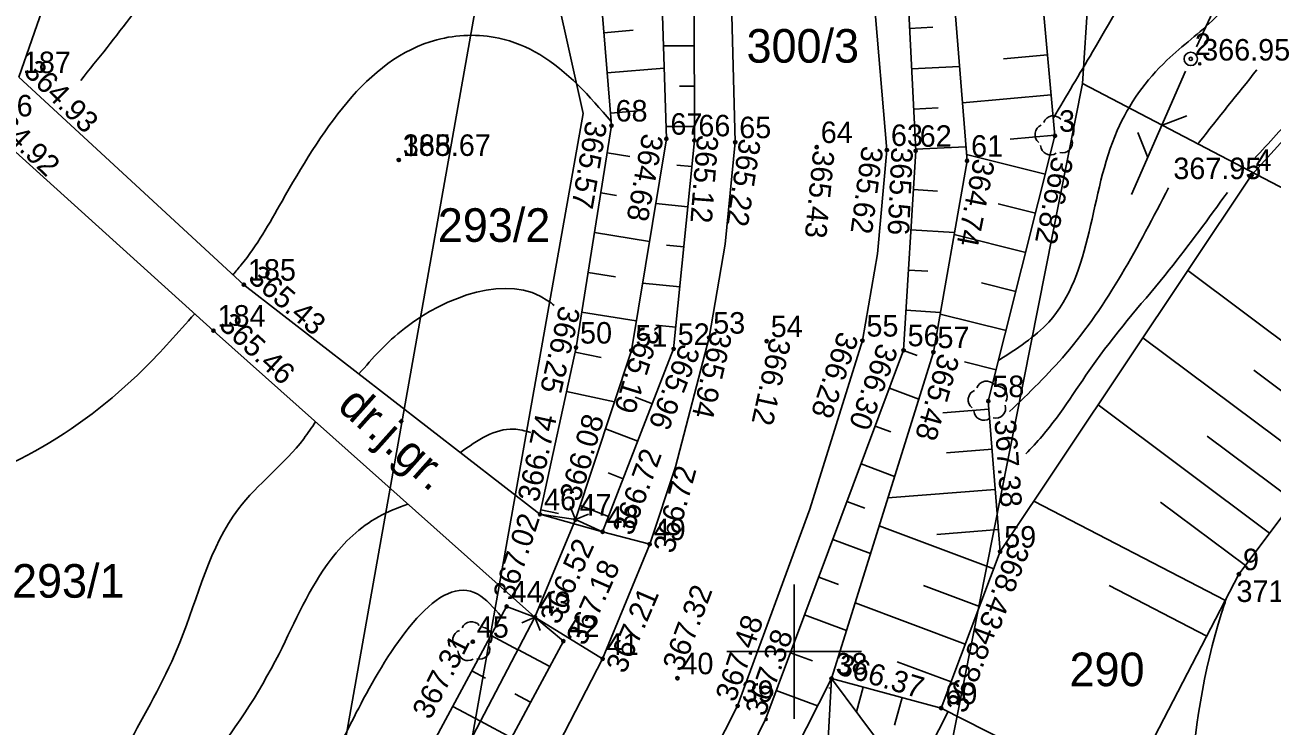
# Model space of a CAD drawing. Extents: x 4635329 to 4651863, y 5356628 to 5367582.
# Drawn here: x 4651721.4 to 4651767.77, y 5357047.23 to 5357073.31 of the extents above; entities that cross this region are included whole.
import ezdxf

# ---------------------------------------------------------------- set-up
doc = ezdxf.new("R2010")
doc.units = 0
for name, color, linetype in [('Level 20', 7, 'Continuous'), ('Level 21', 7, 'Continuous'), ('Level 24', 7, 'Continuous'), ('Level 32', 7, 'Continuous'), ('Level 4', 7, 'Continuous'), ('Level 44', 7, 'Continuous'), ('Level 45', 7, 'Continuous'), ('Level 46', 7, 'Continuous'), ('Level 48', 7, 'Continuous'), ('Level 5', 7, 'Continuous'), ('Level 50', 7, 'Continuous'), ('Level 55', 7, 'Continuous'), ('Level 60', 7, 'Continuous'), ('Level 63', 7, 'Continuous')]:
    doc.layers.add(name, color=color, linetype=linetype)

msp = doc.modelspace()

# ---------------------------------------------------------------- linework, layer by layer
at = {"layer": 'Level 20'}
for p, q in [((4651752.38, 5357081.18), (4651753.45, 5357068.66)), ((4651747.9, 5357047.98), (4651742.26, 5357036.94))]:
    msp.add_line(p, q, dxfattribs=at)
for points in [[(4651729.32, 5357025.03), (4651737.42, 5357039.16), (4651742.88, 5357049.73), (4651744.63, 5357054), (4651745.586, 5357056.87), (4651746.84, 5357061.68), (4651747.431, 5357065.159), (4651747.81, 5357068.95), (4651747.54, 5357079.35), (4651746.07, 5357086.39), (4651738.98, 5357107.74), (4651737.87, 5357110.18), (4651736.57, 5357115.87), (4651735.37, 5357118.93)], [(4651724.46, 5357080.82), (4651721.17, 5357071.37)], [(4651744.63, 5357054), (4651742.88, 5357054.46), (4651740.55, 5357055.11), (4651729.54, 5357063.65), (4651721.17, 5357071.37)], [(4651719.75, 5357069.76), (4651728.41, 5357061.94), (4651740.36, 5357051.28), (4651742.88, 5357049.73)], [(4651753.45, 5357068.66), (4651753.095, 5357064.795), (4651752.54, 5357061.57)], [(4651752.54, 5357061.57), (4651750.584, 5357055.295), (4651747.9, 5357047.98)]]:
    msp.add_lwpolyline(points, dxfattribs=at)
at = {"layer": 'Level 24'}
for p, q in [((4651741.87, 5357054.91), (4651741.668, 5357055.4)), ((4651742.36, 5357055.112), (4651741.87, 5357054.91)), ((4651741.87, 5357054.91), (4651740.36, 5357051.28)), ((4651739.87, 5357051.078), (4651740.36, 5357051.28)), ((4651740.36, 5357051.28), (4651740.562, 5357050.79))]:
    msp.add_line(p, q, dxfattribs=at)
at = {"layer": 'Level 32'}
for p, q in [((4651764.961, 5357072.503), (4651767.07, 5357077.037)), ((4651764.55, 5357071.592), (4651762.549, 5357067.009)), ((4651763.667, 5357069.569), (4651764.598, 5357069.934)), ((4651763.149, 5357068.384), (4651762.784, 5357069.315))]:
    msp.add_line(p, q, dxfattribs=at)
msp.add_circle((4651764.75, 5357072.05), 0.25, dxfattribs=at)
at = {"layer": 'Level 4'}
for p, q in [((4651739.54, 5357081.79), (4651731.74, 5357037.85)), ((4651742.153, 5357070.018), (4651739.54, 5357081.79)), ((4651760.94, 5357074.531), (4651760.729, 5357071.135)), ((4651760.729, 5357071.135), (4651755.332, 5357043.962)), ((4651760.729, 5357071.135), (4651781.491, 5357060.254)), ((4651737.245, 5357042.436), (4651742.153, 5357070.018))]:
    msp.add_line(p, q, dxfattribs=at)
at = {"layer": 'Level 44'}
for centre in [(4651765.083, 5357071.868), (4651743.21, 5357069.57), (4651745.25, 5357069.08), (4651746.29, 5357069.02), (4651747.81, 5357068.95), (4651759.7, 5357069.19), (4651750.84, 5357068.77), (4651753.45, 5357068.66), (4651754.52, 5357068.63), (4651735.3, 5357068.29), (4651756.43, 5357068.26), (4651767.01, 5357067.73), (4651729.54, 5357063.65), (4651728.41, 5357061.94), (4651746.84, 5357061.68), (4651748.98, 5357061.55), (4651752.54, 5357061.57), (4651741.89, 5357061.31), (4651743.95, 5357061.2), (4651745.52, 5357061.26), (4651754.07, 5357061.21), (4651755.18, 5357061.14), (4651757.22, 5357059.32), (4651740.55, 5357055.11), (4651741.87, 5357054.91), (4651742.88, 5357054.46), (4651744.63, 5357054), (4651757.66, 5357053.72), (4651766.54, 5357052.88), (4651739.31, 5357051.68), (4651740.36, 5357051.28), (4651741.42, 5357050.39), (4651738.05, 5357050.37), (4651742.88, 5357049.73), (4651745.66, 5357049.01), (4651751.39, 5357049), (4651747.9, 5357047.98), (4651755.47, 5357047.9), (4651748.961, 5357047.48)]:
    msp.add_circle(centre, 0.04, dxfattribs=at)
at = {"layer": 'Level 46'}
for points in [[(4651759.64, 5357069.854), (4651761.095, 5357072.307), (4651763.521, 5357076.401), (4651765.794, 5357079.585), (4651768.674, 5357082.223), (4651772.525, 5357084.498), (4651783.153, 5357090.274), (4651784.378, 5357091.117)], [(4651723.473, 5357071.251), (4651725.409, 5357073.711), (4651731.503, 5357081.232), (4651732.299, 5357081.873)], [(4651757.599, 5357060.829), (4651759.467, 5357062.262), (4651762.013, 5357069.388), (4651763.863, 5357071.997), (4651765.651, 5357073.573), (4651768.501, 5357077.425), (4651770.563, 5357079.778)], [(4651767.105, 5357068.328), (4651768.709, 5357070.15), (4651771.135, 5357073.607), (4651771.248, 5357073.748)], [(4651743.198, 5357069.717), (4651740.539, 5357072.214), (4651739.023, 5357072.821), (4651736.719, 5357072.76), (4651730.959, 5357066.756), (4651729.443, 5357064.39), (4651729.134, 5357064.025)], [(4651764.995, 5357068.861), (4651765.063, 5357068.948), (4651767.21, 5357071.644)], [(4651758.015, 5357058.929), (4651760.096, 5357061.072), (4651763.924, 5357067.256)], [(4651758.618, 5357057.356), (4651759.22, 5357058.019), (4651761.221, 5357060.809), (4651763.95, 5357064.206), (4651766.113, 5357067.084)], [(4651766.724, 5357038.681), (4651767.527, 5357043.066), (4651768.496, 5357049.151), (4651769.132, 5357051.698), (4651771.164, 5357054.488), (4651775.611, 5357060.263), (4651778.248, 5357062.295), (4651781.341, 5357064.6), (4651784.16, 5357065.358), (4651784.354, 5357065.321)], [(4651733.818, 5357060.331), (4651735.51, 5357062.024), (4651740.846, 5357063.055), (4651741.076, 5357062.881)], [(4651727.711, 5357062.571), (4651725.805, 5357060.508), (4651717.074, 5357055.838), (4651713.254, 5357055.717), (4651704.374, 5357054.513), (4651699.766, 5357053.179), (4651694.309, 5357052.33), (4651693.661, 5357052)], [(4651725.331, 5357046.729), (4651727.157, 5357050.339), (4651729.34, 5357055.312), (4651731.765, 5357057.92), (4651732.207, 5357058.553)], [(4651737.589, 5357057.407), (4651739.57, 5357058.277), (4651740.204, 5357058.158)], [(4651694.191, 5357036.621), (4651700.772, 5357038.944), (4651708.048, 5357039.732), (4651714.051, 5357039.49), (4651719.144, 5357039.793), (4651728.057, 5357045.676), (4651730.846, 5357049.922), (4651732.786, 5357053.44), (4651734.545, 5357055.017), (4651735.638, 5357055.492)], [(4651739.11, 5357051.308), (4651738.239, 5357052.138), (4651733.994, 5357048.256), (4651732.66, 5357045.769), (4651728.598, 5357041.705), (4651724.147, 5357038.834)], [(4651764.562, 5357041.452), (4651764.711, 5357044.761), (4651765.893, 5357051.433), (4651766.067, 5357051.967)]]:
    msp.add_spline(points, degree=3, dxfattribs=at)
at = {"layer": 'Level 48'}
for p, q in [((4651754.293, 5357073.181), (4651755.161, 5357073.224)), ((4651742.925, 5357073.025), (4651744.021, 5357073.115)), ((4651746.283, 5357072.538), (4651745.138, 5357072.536)), ((4651754.368, 5357071.683), (4651756.148, 5357071.771)), ((4651759.426, 5357072.204), (4651757.782, 5357072.054)), ((4651743.048, 5357071.53), (4651745.165, 5357071.704)), ((4651746.286, 5357071.038), (4651745.736, 5357071.037)), ((4651759.562, 5357070.71), (4651756.257, 5357070.409)), ((4651743.172, 5357070.035), (4651744.193, 5357070.119)), ((4651754.442, 5357070.184), (4651755.355, 5357070.23)), ((4651746.289, 5357069.538), (4651745.236, 5357069.536)), ((4651759.698, 5357069.216), (4651758.037, 5357069.065)), ((4651743.047, 5357068.549), (4651743.886, 5357068.415)), ((4651754.517, 5357068.686), (4651756.388, 5357068.78)), ((4651746.193, 5357068.043), (4651745.645, 5357068.097)), ((4651759.341, 5357067.761), (4651756.41, 5357068.497)), ((4651754.433, 5357067.189), (4651755.328, 5357067.135)), ((4651742.81, 5357067.068), (4651743.398, 5357066.974)), ((4651746.045, 5357066.55), (4651744.852, 5357066.669)), ((4651758.975, 5357066.306), (4651757.592, 5357066.653)), ((4651742.574, 5357065.587), (4651744.62, 5357065.26)), ((4651754.342, 5357065.692), (4651755.962, 5357065.593)), ((4651758.61, 5357064.851), (4651755.949, 5357065.52)), ((4651745.897, 5357065.058), (4651745.252, 5357065.122)), ((4651742.337, 5357064.106), (4651743.356, 5357063.943)), ((4651754.251, 5357064.194), (4651754.976, 5357064.151)), ((4651771.276, 5357059.209), (4651764.638, 5357064.176)), ((4651745.749, 5357063.565), (4651744.363, 5357063.703)), ((4651758.244, 5357063.396), (4651756.967, 5357063.717)), ((4651742.1, 5357062.625), (4651744.132, 5357062.3)), ((4651754.16, 5357062.697), (4651755.44, 5357062.62)), ((4651757.879, 5357061.941), (4651755.429, 5357062.557)), ((4651745.601, 5357062.072), (4651744.859, 5357062.146)), ((4651769.479, 5357056.807), (4651762.97, 5357061.677)), ((4651741.854, 5357061.145), (4651742.824, 5357060.936)), ((4651754.066, 5357061.201), (4651754.574, 5357061.011)), ((4651757.513, 5357060.487), (4651756.337, 5357060.782)), ((4651770.377, 5357058.008), (4651767.091, 5357060.467)), ((4651753.541, 5357059.796), (4651754.633, 5357059.387)), ((4651741.537, 5357059.679), (4651743.32, 5357059.294)), ((4651744.73, 5357059.224), (4651744.095, 5357059.471)), ((4651757.243, 5357059.024), (4651755.534, 5357058.889)), ((4651767.681, 5357054.405), (4651761.303, 5357059.178)), ((4651753.015, 5357058.391), (4651753.6, 5357058.172)), ((4651744.187, 5357057.826), (4651742.988, 5357058.291)), ((4651768.58, 5357055.606), (4651765.358, 5357058.017)), ((4651757.361, 5357057.528), (4651755.665, 5357057.395)), ((4651752.49, 5357056.986), (4651753.737, 5357056.519)), ((4651743.644, 5357056.428), (4651743.08, 5357056.647)), ((4651757.478, 5357056.033), (4651753.488, 5357055.719)), ((4651751.964, 5357055.581), (4651752.627, 5357055.333)), ((4651766.036, 5357051.908), (4651758.915, 5357055.6)), ((4651766.783, 5357053.204), (4651763.626, 5357055.566)), ((4651740.587, 5357055.281), (4651741.243, 5357055.139)), ((4651743.101, 5357055.029), (4651742.045, 5357055.439)), ((4651757.421, 5357053.084), (4651753.165, 5357054.685)), ((4651751.439, 5357054.176), (4651752.842, 5357053.651)), ((4651757.596, 5357054.538), (4651755.301, 5357054.357)), ((4651750.913, 5357052.771), (4651751.654, 5357052.494)), ((4651756.892, 5357051.68), (4651754.805, 5357052.465)), ((4651765.345, 5357050.576), (4651761.711, 5357052.46)), ((4651756.364, 5357050.276), (4651752.269, 5357051.817)), ((4651750.388, 5357051.366), (4651751.947, 5357050.783)), ((4651738.732, 5357050.605), (4651739.728, 5357050.069)), ((4651740.911, 5357049.443), (4651739.732, 5357050.076)), ((4651749.862, 5357049.961), (4651750.68, 5357049.655)), ((4651755.836, 5357048.872), (4651753.829, 5357049.627)), ((4651738.021, 5357049.284), (4651738.527, 5357049.011)), ((4651751.371, 5357048.644), (4651751.292, 5357048.649)), ((4651752.565, 5357048.683), (4651752.316, 5357047.76)), ((4651740.201, 5357048.121), (4651739.619, 5357048.434)), ((4651749.337, 5357048.556), (4651750.873, 5357047.981)), ((4651754.013, 5357048.293), (4651753.735, 5357047.262)), ((4651737.31, 5357047.963), (4651738.339, 5357047.409)), ((4651755.723, 5357047.772), (4651755.032, 5357046.41)), ((4651739.492, 5357046.8), (4651738.343, 5357047.417))]:
    msp.add_line(p, q, dxfattribs=at)
for points in [[(4651737.79, 5357107.28), (4651744.63, 5357085.99), (4651746.27, 5357078.87), (4651746.29, 5357069.02), (4651745.52, 5357061.26), (4651742.88, 5357054.46)], [(4651741.87, 5357054.91), (4651743.95, 5357061.2), (4651745.25, 5357069.08), (4651744.94, 5357078.65), (4651743.36, 5357085.8), (4651736.77, 5357106.89)], [(4651735.92, 5357106.43), (4651735.39, 5357102.29), (4651740.66, 5357084.52), (4651742.61, 5357076.85), (4651743.21, 5357069.57), (4651741.89, 5357061.31), (4651740.55, 5357055.11)], [(4651735.13, 5357022.17), (4651743.48, 5357036.33), (4651748.947, 5357047.515), (4651754.07, 5357061.21), (4651754.52, 5357068.63), (4651753.87, 5357081.66), (4651752.46, 5357088.23), (4651750.47, 5357096.71)], [(4651751.75, 5357096.48), (4651753.65, 5357088.45), (4651755.38, 5357081.36), (4651756.43, 5357068.26), (4651755.18, 5357061.14), (4651751.39, 5357049), (4651749.99, 5357046.24), (4651744.18, 5357035.62), (4651736.09, 5357021.66)], [(4651769.53, 5357089.73), (4651761.64, 5357093.28), (4651755.56, 5357094.47), (4651758.57, 5357081.61), (4651759.7, 5357069.19), (4651757.22, 5357059.32), (4651757.66, 5357053.72), (4651755.47, 5357047.9), (4651751.39, 5357049)], [(4651757.66, 5357053.72), (4651767.01, 5357067.73), (4651777.8, 5357079.65), (4651784.84, 5357080.88)], [(4651784.84, 5357080.88), (4651781.73, 5357068.02), (4651773.05, 5357061.58), (4651766.54, 5357052.88), (4651762.19, 5357044.49)], [(4651742.88, 5357054.46), (4651741.87, 5357054.91), (4651740.55, 5357055.11)], [(4651726.3, 5357026.64), (4651732.58, 5357039.17), (4651739.31, 5357051.68)], [(4651739.31, 5357051.68), (4651740.36, 5357051.28), (4651741.42, 5357050.39)], [(4651740.36, 5357051.28), (4651734.72, 5357040.48), (4651727, 5357026.25)], [(4651728.28, 5357025.58), (4651735.71, 5357039.76), (4651741.42, 5357050.39)], [(4651750.8, 5357038.16), (4651751.39, 5357049)], [(4651762.19, 5357044.49), (4651755.47, 5357047.9)]]:
    msp.add_lwpolyline(points, dxfattribs=at)
at = {"layer": 'Level 50'}
msp.add_line((4651751.39, 5357049), (4651757.69, 5357040.56), dxfattribs=at)
at = {"layer": 'Level 55'}
for centre in [(4651759.7, 5357069.19), (4651757.22, 5357059.32), (4651738.05, 5357050.37)]:
    msp.add_circle(centre, 0.045, dxfattribs=at)
for centre, start, end in [((4651759.633, 5357069.559), 40.3488, 160.1306), ((4651759.329, 5357069.24), 112.4389, 232.0902), ((4651760.03, 5357069.368), 328.348, 88.132), ((4651759.971, 5357068.931), 256.3906, 16.0419), ((4651759.537, 5357068.852), 184.3875, 304.0933), ((4651756.849, 5357059.37), 112.4389, 232.0902), ((4651757.153, 5357059.689), 40.3488, 160.1306), ((4651757.55, 5357059.498), 328.348, 88.132), ((4651757.057, 5357058.982), 184.3875, 304.0933), ((4651757.491, 5357059.061), 256.3906, 16.0419), ((4651737.999, 5357050.742), 37.8655, 157.6473), ((4651738.388, 5357050.533), 325.8648, 85.6487), ((4651737.681, 5357050.437), 109.9556, 229.607), ((4651737.873, 5357050.04), 181.9043, 301.61), ((4651738.309, 5357050.099), 253.9073, 13.5587)]:
    msp.add_arc(centre, 0.375, start, end, dxfattribs=at)
at = {"layer": 'Level 60'}
for p, q in [((4651750, 5357047.5), (4651750, 5357052.5)), ((4651747.5, 5357050), (4651752.5, 5357050))]:
    msp.add_line(p, q, dxfattribs=at)
at = {"layer": 'Level 63'}
for centre in [(4651764.75, 5357072.05), (4651743.21, 5357069.57), (4651745.25, 5357069.08), (4651746.29, 5357069.02), (4651747.81, 5357068.95), (4651759.7, 5357069.19), (4651750.84, 5357068.77), (4651753.45, 5357068.66), (4651754.52, 5357068.63), (4651735.3, 5357068.29), (4651756.43, 5357068.26), (4651767.01, 5357067.73), (4651729.54, 5357063.65), (4651728.41, 5357061.94), (4651746.84, 5357061.68), (4651748.98, 5357061.55), (4651752.54, 5357061.57), (4651741.89, 5357061.31), (4651743.95, 5357061.2), (4651745.52, 5357061.26), (4651754.07, 5357061.21), (4651755.18, 5357061.14), (4651757.22, 5357059.32), (4651740.55, 5357055.11), (4651741.87, 5357054.91), (4651742.88, 5357054.46), (4651744.63, 5357054), (4651757.66, 5357053.72), (4651766.54, 5357052.88), (4651739.31, 5357051.68), (4651740.36, 5357051.28), (4651738.05, 5357050.37), (4651741.42, 5357050.39), (4651742.88, 5357049.73), (4651745.66, 5357049.01), (4651751.39, 5357049), (4651747.9, 5357047.98), (4651755.47, 5357047.9)]:
    msp.add_circle(centre, 0.06, dxfattribs=at)

# ---------------------------------------------------------------- texts
at = {"layer": 'Level 21'}
msp.add_text('dr.j.gr.', height=1.25, rotation=318.2654, dxfattribs=at).set_placement((4651732.968, 5357059.06))
at = {"layer": 'Level 45'}
for s, p in [('366.95', (4651765.173, 5357071.988)), ('365.67', (4651735.45, 5357068.44)), ('367.95', (4651764.101, 5357067.577)), ('371.12', (4651766.448, 5357051.848))]:
    msp.add_text(s, height=0.8, dxfattribs=at).set_placement(p)
for s, rotation, p in [('364.93', 315.4309, (4651721.311, 5357071.527)), ('364.92', 315.8455, (4651719.867, 5357069.899)), ('365.57', 260.3722, (4651742.265, 5357069.782)), ('364.68', 259.4792, (4651744.363, 5357069.309)), ('365.12', 265.5805, (4651746.393, 5357069.236)), ('365.22', 261.3249, (4651747.977, 5357069.12)), ('365.43', 264.4555, (4651750.711, 5357068.677)), ('365.62', 262.4822, (4651752.525, 5357068.843)), ('365.56', 267.4584, (4651753.621, 5357068.777)), ('364.74', 258.5999, (4651756.689, 5357068.377)), ('366.82', 258.5428, (4651759.603, 5357068.458)), ('365.43', 319.6872, (4651729.654, 5357063.835)), ('365.46', 317.3586, (4651728.57, 5357062.093)), ('366.25', 256.9832, (4651741.282, 5357062.911)), ('365.19', 252.7516, (4651744.267, 5357062.148)), ('365.94', 257.1071, (4651746.926, 5357061.975)), ('366.12', 257.6653, (4651749.112, 5357061.72)), ('366.28', 251.4526, (4651751.658, 5357061.956)), ('365.96', 248.2468, (4651745.789, 5357061.497)), ('366.30', 250.2433, (4651753.13, 5357061.519)), ('365.48', 254.0087, (4651755.391, 5357061.14)), ('366.08', 73.6546, (4651742.025, 5357055.548)), ('366.74', 77.7719, (4651740.488, 5357055.528)), ('367.38', 274.1398, (4651757.447, 5357058.61)), ('366.72', 69.9867, (4651743.974, 5357054.28)), ('366.72', 74.8466, (4651745.521, 5357053.62)), ('367.02', 71.9685, (4651739.543, 5357051.859)), ('366.52', 65.8456, (4651741.246, 5357050.972)), ('368.43', 249.025, (4651758.034, 5357054.079)), ('367.18', 66.2552, (4651742.224, 5357050.186)), ('367.32', 69.4742, (4651745.831, 5357049.222)), ('367.21', 66.9149, (4651743.71, 5357049.147)), ('367.48', 71.0643, (4651747.807, 5357048.089)), ('368.84', 69.7357, (4651756.377, 5357047.669)), ('367.31', 62.9132, (4651736.473, 5357047.433)), ('367.38', 71.0643, (4651748.912, 5357047.558)), ('366.37', 343.4909, (4651751.543, 5357049.178))]:
    msp.add_text(s, height=0.8, rotation=rotation, dxfattribs=at).set_placement(p)
at = {"layer": 'Level 5'}
for s, p in [('300/3', (4651748.232, 5357071.909)), ('293/2', (4651736.752, 5357065.243)), ('293/1', (4651720.919, 5357052.007)), ('290', (4651760.242, 5357048.715))]:
    msp.add_text(s, height=1.25, dxfattribs=at).set_placement(p)
at = {"layer": 'Level 63'}
for s, p in [('2', (4651764.9, 5357072.2)), ('187', (4651721.32, 5357071.52)), ('186', (4651719.9, 5357069.91)), ('68', (4651743.36, 5357069.72)), ('67', (4651745.4, 5357069.23)), ('66', (4651746.44, 5357069.17)), ('65', (4651747.96, 5357069.1)), ('3', (4651759.85, 5357069.34)), ('64', (4651750.99, 5357068.92)), ('63', (4651753.6, 5357068.81)), ('62', (4651754.67, 5357068.78)), ('188', (4651735.45, 5357068.44)), ('61', (4651756.58, 5357068.41)), ('4', (4651767.16, 5357067.88)), ('185', (4651729.69, 5357063.8)), ('184', (4651728.56, 5357062.09)), ('53', (4651746.99, 5357061.83)), ('54', (4651749.13, 5357061.7)), ('55', (4651752.69, 5357061.72)), ('50', (4651742.04, 5357061.46)), ('51', (4651744.1, 5357061.35)), ('52', (4651745.67, 5357061.41)), ('56', (4651754.22, 5357061.36)), ('57', (4651755.33, 5357061.29)), ('58', (4651757.37, 5357059.47)), ('46', (4651740.7, 5357055.26)), ('47', (4651742.02, 5357055.06)), ('48', (4651743.03, 5357054.61)), ('49', (4651744.78, 5357054.15)), ('59', (4651757.81, 5357053.87)), ('9', (4651766.69, 5357053.03)), ('44', (4651739.46, 5357051.83)), ('43', (4651740.51, 5357051.43)), ('45', (4651738.2, 5357050.52)), ('42', (4651741.57, 5357050.54)), ('41', (4651743.03, 5357049.88)), ('40', (4651745.81, 5357049.16)), ('38', (4651751.54, 5357049.15)), ('39', (4651748.05, 5357048.13)), ('60', (4651755.62, 5357048.05))]:
    msp.add_text(s, height=0.8, dxfattribs=at).set_placement(p)

doc.saveas('drawing.dxf')
